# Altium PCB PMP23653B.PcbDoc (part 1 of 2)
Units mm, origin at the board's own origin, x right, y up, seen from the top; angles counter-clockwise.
Board outline 60 x 20 mm, 4 copper layers (Top Layer, Layer 2, Layer 3, Bottom Layer), stack 1.509 mm thick; 89 components, 44 nets, 290 pads, 82 vias.
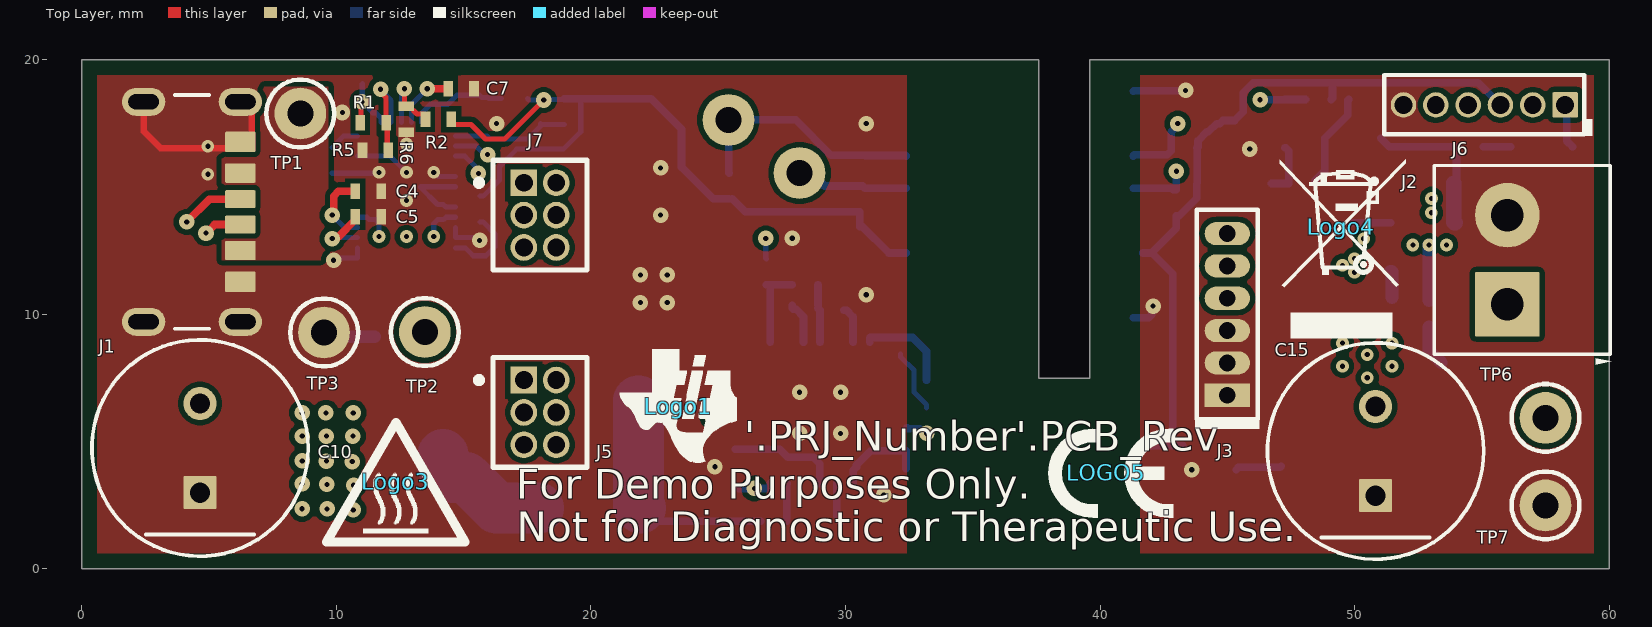
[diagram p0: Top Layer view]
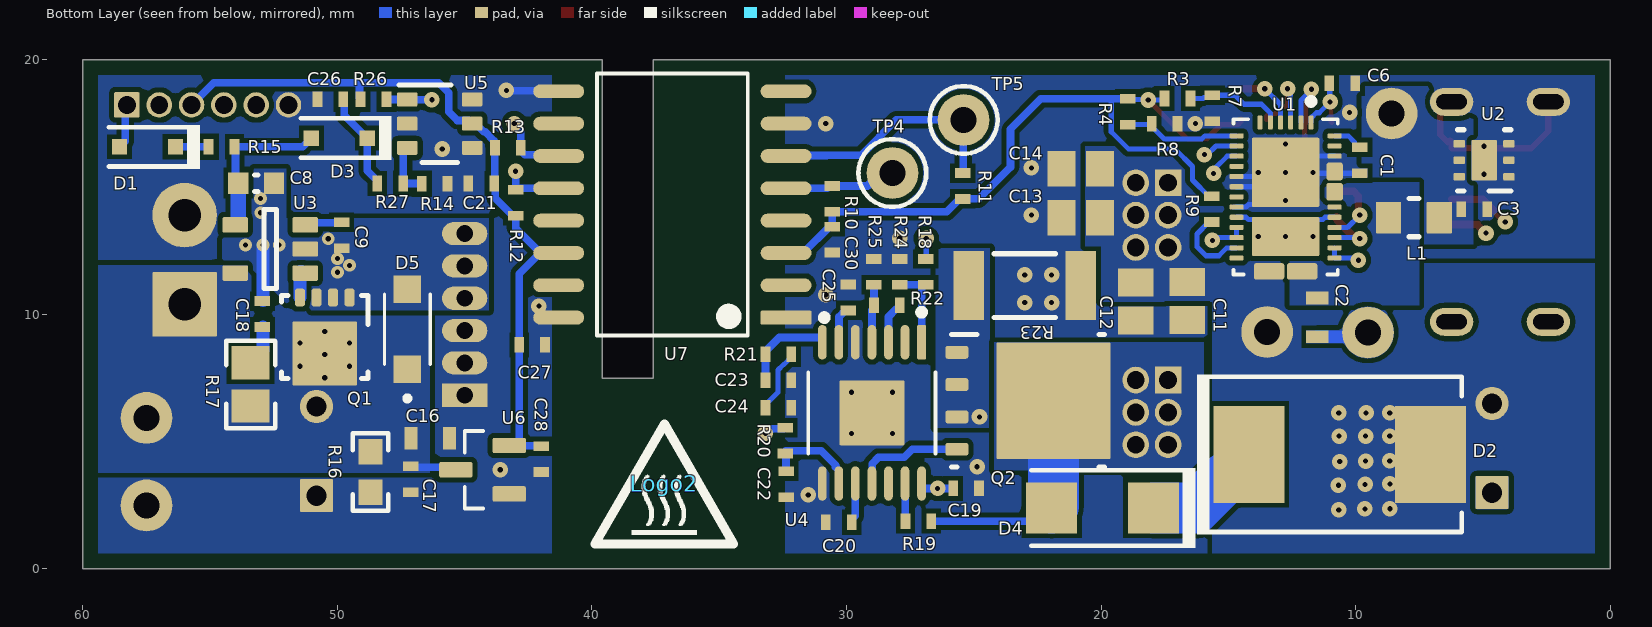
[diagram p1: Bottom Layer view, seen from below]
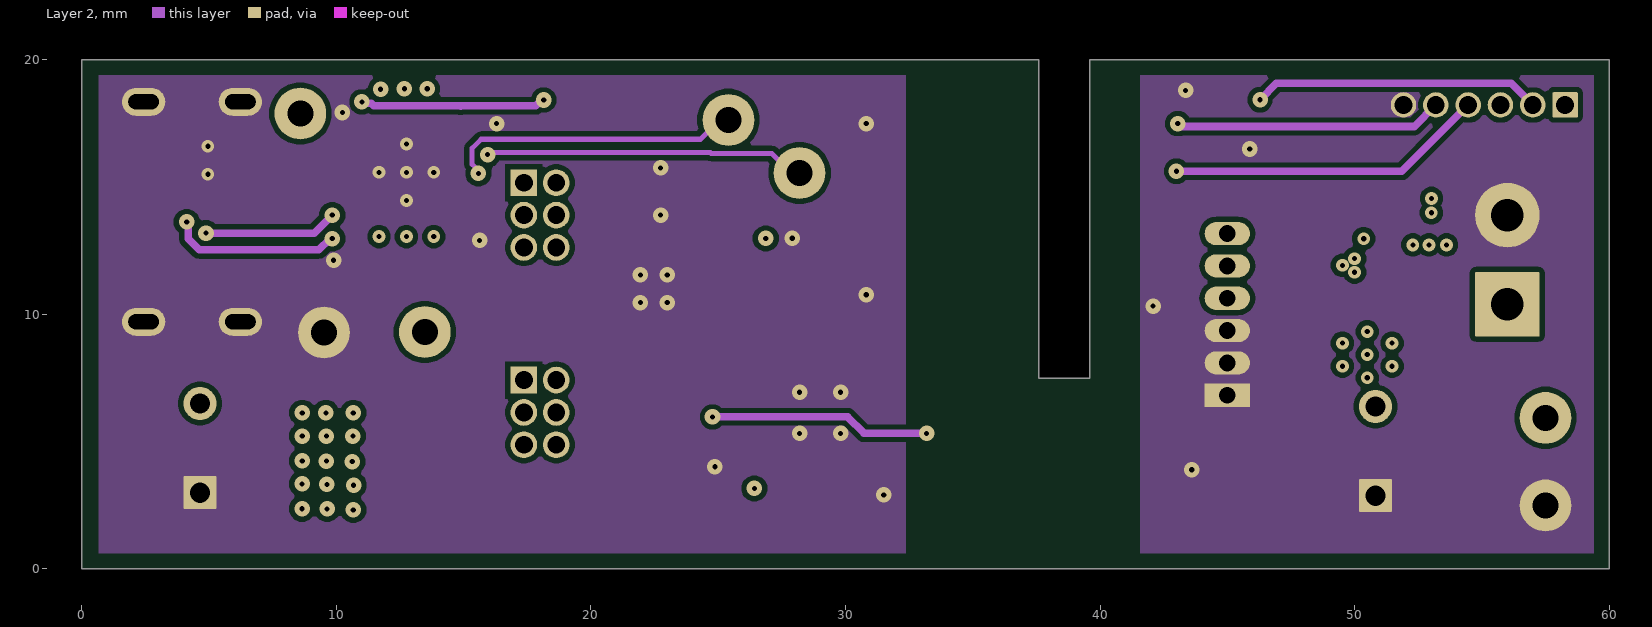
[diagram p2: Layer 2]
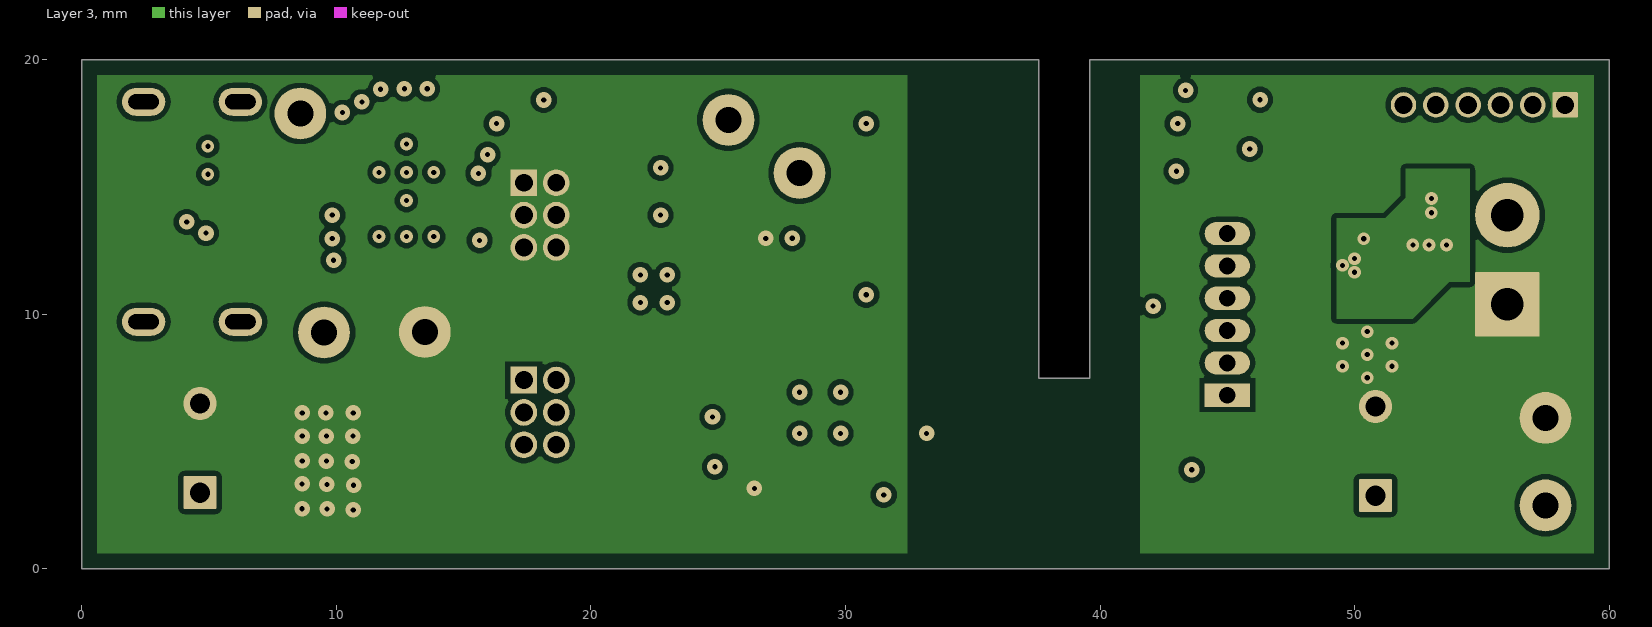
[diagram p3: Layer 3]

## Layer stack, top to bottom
Top Solder: solder mask 0.0254, SM-001, Dk 4
Top Layer: signal copper 0.07
Dielectric 1: prepreg 0.1295, PP-017, Dk 4.3
Dielectric 2: prepreg 0.1295, PP-017, Dk 4.3
Layer 2: signal copper 0.07
Dielectric 3: core 0.7112, Core-039, Dk 4.8
Layer 3: signal copper 0.07
Dielectric 4: prepreg 0.1295, PP-017, Dk 4.3
Dielectric 5: prepreg 0.1295, PP-017, Dk 4.3
Bottom Layer: signal copper 0.07
Bottom Solder: solder mask 0.0254, SM-001, Dk 4

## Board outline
0,0 0,20 37.6,20 37.6,7.5 39.6,7.5 39.6,20 60,20 60,0

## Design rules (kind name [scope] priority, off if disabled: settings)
AcuteAngle [All] p1: minimum=4.50000000000000E+0001 checktracksonly=FALSE
AssemblyTestPointUsage [All] p1: valid=2
BoardOutlineClearance BoardOutlineClearance_MountingHoles [OnCopper and InComponentClass('Mounting Holes')] p1: gap=0.6 ignorepadtopadclearanceinfootprint=FALSE
BoardOutlineClearance BoardOutlineClearance_Poly [OnCopper and IsPoly] p2: gap=0.6 ignorepadtopadclearanceinfootprint=FALSE
BoardOutlineClearance [OnCopper and Not InComponentClass('Logo') and not InComponentClass('FiducialMark') and not InRegion(1000,500,4000,800) and not InPoly] p3: gap=0.6 ignorepadtopadclearanceinfootprint=FALSE
Clearance Clearance_Keepouts [((IsTrack Or IsArc) And Not InPoly) And IsFree and IsKeepOut vs ((IsTrack Or IsArc) And Not InPoly) And IsFree and IsKeepOut] p1: gap=0 ignorepadtopadclearanceinfootprint=FALSE
Clearance Clearance_Poly [InPolygon] p2: gap=0.2 ignorepadtopadclearanceinfootprint=TRUE
Clearance Clearance_FiducialMark [IsKeepOut and InComponentClass('FiducialMark') vs IsPad and InComponentClass('FiducialMark')] p3: gap=0 ignorepadtopadclearanceinfootprint=FALSE
Clearance [All] p4: gap=0.2 ignorepadtopadclearanceinfootprint=TRUE
ComponentClearance ComponentClearance_MountingHoles_FiducialMarks [InComponentClass('Mounting Holes') vs InComponentClass('FiducialMark')] p1: gap=1.27 collisioncheckmode=3 verticalgap=0.254 showdistances=FALSE
ComponentClearance ComponentClearance_Shunt [InComponentClass('Header') vs InComponentClass('Shunt')] p2: gap=0 collisioncheckmode=3 verticalgap=0 showdistances=FALSE
ComponentClearance ComponentClearance_Logo [InComponentClass('Logo')] p3: gap=0.762 collisioncheckmode=3 verticalgap=0.254 showdistances=FALSE
ComponentClearance ComponentClearance_ScrewToNut [(HasFootprint('NY PMS 440 0025 PH')) vs (HasFootprint('Keystone_1902C'))] p4: gap=0.127 collisioncheckmode=3 verticalgap=0.254 showdistances=FALSE
ComponentClearance ComponentClearance_MountingHoles [InComponentClass('Mounting Holes')] p5: gap=2.54 collisioncheckmode=3 verticalgap=2540 showdistances=FALSE
ComponentClearance ComponentClearance_SmallPassives [HasFootprint('0201*') or HasFootprint('0402*') or HasFootprint('0508') or HasFootprint('0603*') or HasFootprint('0612') or HasFootprint('0805*') or HasFootprint('0815*') or HasFootprint('0830*') or HasFootprint('1206*') or HasFootprint('1210*') or HasFootprint('1808*') or HasFootprint('1812*') or HasFootprint('1825*') or HasFootprint('2010*') or HasFootprint('2220*') or HasFootprint('2225*') or HasFootprint('2512*') or HasFootprint('2728*') or HasFootprint('3518*') vs HasFootprint('0201*') or HasFootprint('0402*') or HasFootprint('0508') or HasFootprint('0603*') or HasFootprint('0612') or HasFootprint('0805*') or HasFootprint('0815*') or HasFootprint('0830*') or HasFootprint('1206*') or HasFootprint('1210*') or HasFootprint('1808*') or HasFootprint('1812*') or HasFootprint('1825*') or HasFootprint('2010*') or HasFootprint('2220*') or HasFootprint('2225*') or HasFootprint('2512*') or HasFootprint('2728*') or HasFootprint('3518*')] p6: gap=0.38 collisioncheckmode=3 verticalgap=0.254 showdistances=FALSE
ComponentClearance ComponentClearance_THtoSMT [IsThruComponent vs IsSMTComponent] p7: gap=0.762 collisioncheckmode=3 verticalgap=0.762 showdistances=FALSE
ComponentClearance ComponentClearance_THtoTH [IsThruComponent vs IsThruComponent] p8: gap=0.508 collisioncheckmode=3 verticalgap=0.762 showdistances=FALSE
ComponentClearance [All] p9: gap=0.508 collisioncheckmode=3 verticalgap=0.254 showdistances=FALSE
DiffPairsRouting [All] p1: maxlimit=2.54 minlimit=0.254 mostfreqgap=0.254 toplayer_minwidth=0.381 toplayer_maxwidth=0.381 toplayer_prefwidth=0.381 midlayer1_minwidth=0.381 midlayer1_maxwidth=0.381 midlayer1_prefwidth=0.381 midlayer2_minwidth=0.381 midlayer2_maxwidth=0.381 midlayer2_prefwidth=0.381 bottomlayer_minwidth=0.381 bottomlayer_maxwidth=0.381 bottomlayer_prefwidth=0.381 maxuncoupledlength=25.4
FabricationTestPointUsage TestPointUsage [All] p1: valid=2 allowmultiple=FALSE
FabricationTestpoint Testpoint [All] p1: side=3 testpointundercomponent=TRUE minsize=1.016 maxsize=2.54 preferedsize=1.524 minholesize=0 maxholesize=1.016 preferedholesize=0.813 testpointgrid=0.025 allowsidetop=TRUE allowsidebottom=TRUE usegrid=TRUE gridtolerance=0
FanoutControl Fanout_LCC [IsLCC] p1: bgadir=Out bgaviamode=Centered fanoutstyle=Auto fanoutdirection=Alternating viagrid=0.025 // Fanout_LCC (Default Rule)
FanoutControl Fanout_BGA [IsBGA] p2: bgadir=Out bgaviamode=Centered fanoutstyle=Auto fanoutdirection=Alternating viagrid=0.025 // Fanout_BGA (Default Rule)
FanoutControl Fanout_Default [All] p4: bgadir=Out bgaviamode=Centered fanoutstyle=Auto fanoutdirection=Alternating viagrid=0.025 // Fanout_Default (Default Rule)
FanoutControl Fanout_Small [(CompPinCount < 5)] p5: bgadir=Out bgaviamode=Centered fanoutstyle=Auto fanoutdirection=OutThenIn viagrid=0.025 // Fanout_Small (Default Rule)
HoleSize [All] p1: absolutevalues=TRUE maxlimit=6.375 minlimit=0.2 maxpercent=80.000 minpercent=20.000
MinimumAnnularRing MinimumAnnularRing_ThermalPadVias [IsVia and InAnyComponent] p1: minimumring=0.15
MinimumAnnularRing [All] p2: minimumring=0.12
MinimumSolderMaskSliver MinimumSolderMaskSliver_Logo [InComponentClass('Logo') vs InComponentClass('Logo')] p1: minsoldermaskwidth=0.018
MinimumSolderMaskSliver [All] p2: minsoldermaskwidth=0.1
PlaneConnect [All] p1: planeconnectstyle=Direct reliefexpansion=0.254 reliefentries=4 reliefconductorwidth=0.254 reliefairgap=0.254
PolygonConnect [All] p1: connectstyle=Direct reliefconductorwidth=0.254 reliefentries=4 polygonreliefangle="90 Angle" airgapwidth=0.254
RoutingVias ThermalPadVias [IsVia and InAnyComponent] p1: holewidth=0.2 width=0.5 viastyle="Through Hole" minholewidth=0.2 minwidth=0.5 maxholewidth=0.33 maxwidth=0.6
RoutingVias [All] p2: holewidth=0.406 width=0.864 viastyle="Through Hole" minholewidth=0.2 minwidth=0.5 maxholewidth=1.016 maxwidth=1.651
SilkToBoardRegionClearance [Not ((IsComment or IsDesignator) And (Hide <> 'False')) and not InRegion(1000,500,4000,800)] p1:
SilkToSilkClearance SilkToSilkClearance_Pb-FreeLogo [(HasFootprint('Pb-Free_Overlay_Medium') OR HasFootprint('Pb-Free_Overlay_Small')) vs (HasFootprint('Pb-Free_Overlay_Medium') OR HasFootprint('Pb-Free_Overlay_Small'))] p1: silktosilkclearance=0
SilkToSilkClearance [All] p2: silktosilkclearance=0.1
SilkToSolderMaskClearance SilkToComponentPadClearance [(IsPad or IsFill or IsRegion) and InAnycomponent] p1: minsilkscreentomaskgap=0.02 clearancetoexposedcopper=TRUE
SilkToSolderMaskClearance "Silk to Solder Mask Opening" [All] p2: minsilkscreentomaskgap=0 clearancetoexposedcopper=FALSE
SolderMaskExpansion [All] p1: expansion=0.05 istentingtop=FALSE
UnRoutedNet [All] p1: checkbadconnections=TRUE
Width [All] p1: maxlimit=2.54 minlimit=0.152 preferedwidth=0.254 checkconnectedcopper=TRUE
14 further rules are at their usual default settings.

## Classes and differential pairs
component class Header: J5 J6 J7
component class PMP23653B_sheet1: C1 C2 C3 C4 C5 C6 C7 J1 L1 R1 R2 R3 R4 R5 R6 R7 R8 R9 R10 R11 TP1 U1 U2
component class Logo: Logo1
component class PMP23653B_sheet2: C8 C9 C10 C11 C12 C13 C14 C15 C16 C17 C18 C19 C20 C21 C22 C23 C24 C25 C26 C27 C28 C30 D1 D2 D3 D4 D5 J2 J3 J5 J6 J7 Logo1 Logo2 Logo3 Logo4 LOGO5 Q1 Q2 R12 R13 R14 R15 R16 R17 R18 R19 R20 R21 R22 R23 R24 R25 R26 R27 TP2 TP3 TP4 TP5 TP6 TP7 U3 U4 U5 U6 U7

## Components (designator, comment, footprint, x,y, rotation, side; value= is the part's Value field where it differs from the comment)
C1 "GRM155R61A106ME44" 0402_070 9.836,16.055 r90 bottom value=10uF
C2 "GRM188R6YA475KE15D" 0603S 11.5,9.883 r270 bottom value=4.7uF
C3 "C1005X7R1H104K050BB" 0402S 5.338,14.122 r180 bottom value=0.1uF
C4 "GRM1555C1H331FA01J" 0402S 11.25,14.831 r180 top value=330pF
C5 "GRM1555C1H331FA01J" 0402S 11.25,13.831 r180 top value=330pF
C6 "GRM155R61A106ME44" 0402_070 10.525,19.072 r0 bottom value=10uF
C7 "GRM155R61A106ME44" 0402_070 14.9,18.862 r180 top value=10uF
C8 "GRM188R71H224KAC4D" 0603L 53.19,15.159 r180 bottom value=0.22uF
C9 "GRM155R61E225KE11D" 0402_070 49.833,13.109 r270 bottom value=2.2uF
C10 "16SEPC180MX" FP-16SEPC180MX_RADIAL-MFG 4.641,4.75 r90 top
C11 "GRM21BR61E226ME44L" 0805L 16.615,10.53 r270 bottom value=22uF
C12 "GRM21BR61E226ME44L" 0805L 18.635,10.506 r270 bottom value=22uF
C13 "GRM21BR61E226ME44L" 0805L 20.8,13.795 r0 bottom value=22uF
C14 "GRM21BR61E226ME44L" 0805L 20.8,15.726 r0 bottom value=22uF
C15 "16SEPC180MX" FP-16SEPC180MX_RADIAL-MFG 50.821,4.631 r90 top
C16 "C1608X5R1E106M080AC" 0603S 46.354,5.131 r0 bottom value=10uF
C17 "CC0402KRX7R8BB104" 0402S 47.116,3.521 r90 bottom value=0.1uF
C18 "GRM1555C1H101JA01D" 0402S 52.945,10.016 r90 bottom value=100pF
C19 "GRM155R61E105MA12D" 0402S 25.3,3.163 r0 bottom value=1uF
C20 "GRM155R61E105MA12D" 0402S 30.305,1.834 r180 bottom value=1uF
C21 "GRM155R61E105MA12D" 0402S 44.35,15.143 r180 bottom value=1uF
C22 "GRM1555C1H101JA01D" 0402S 32.374,3.327 r90 bottom value=100pF
C23 "GRM1555C1H470JZ01" 0402S 32.674,7.42 r180 bottom value=47pF
C24 "GRM155R61C273KA01D" 0402S 32.674,6.334 r180 bottom value=0.027uF
C25 "04023C103JAT2A" 0402S 29.924,10.664 r270 bottom value=0.01uF
C26 "GRM155R71H222KA01D" 0402S 50.275,18.445 r0 bottom value=2200pF
C27 "CC0402KRX7R8BB104" 0402S 42.35,8.8 r0 bottom value=0.1uF
C28 "GRM155R61A106ME44" 0402_070 42,4.315 r90 bottom value=10uF
C30 "CC0402KRX7R8BB104" 0402S 30.553,12.936 r90 bottom value=0.1uF
D1 "BAS16J,135" SOD-323F 57.461,16.586 r0 bottom value=100V
D2 "SMCJ22A-TR" SMC 10.625,4.5 r180 bottom value=22V
D3 "BAS16J,135" SOD-323F 49.923,16.925 r0 bottom value=100V
D4 "MURA110T3G" SMA 19.942,2.397 r0 bottom value=100V
D5 "60V" SODFL3718X102N 47.251,9.415 r90 bottom
J1 "USB4125-GF-A-0190" FP-USB4125-GF-A-0190_CONN_USB-MFG 3.226,14.03 r270 top
J2 "ED555/2DS" TERM_BLK_ED555-2DS 56,10.393 r90 top
J3 "851-43-006-10-001000" Mill-Max_851-XX-006-10-001000 45,10 r270 top
J5 "GRPB032VWVN-RC" Sullins_GRPB032VWVN-RC 18,6.15 r0 top
J6 "GRPB061VWVN-RC" Sullins_GRPB061VWVN-RC 55.095,18.23 r180 top
J7 "GRPB032VWVN-RC" Sullins_GRPB032VWVN-RC 18,13.9 r0 top
L1 "FBMJ2125HM210NT" 0805_HV1 7.707,13.8 r0 bottom value="21 ohm"
Logo1 "Texas Instruments" TI_Symbol_Overlay_Small 23.428,6.395 r0 top
Logo2 "CAUTION HOT SURFACE" IEC_HotSurface_Small 37.156,3.349 r180 bottom
Logo3 "CAUTION HOT SURFACE" IEC_HotSurface_Small 12.333,3.416 r0 top
Logo4 "WEEE logo" WEEE_Minimum 49.483,13.444 r0 top
LOGO5 "CE Mark" CE_Mark_3MM5 40.25,3.78 r0 top
Q1 "CSD18543Q3A" DNH0008A 50.496,9.115 r270 bottom value=60V
Q2 "CSD18514Q5A" DQJ0008A 22.87,6.607 r180 bottom value=40V
R1 "CRCW040210K0FKED" 0402S 11.445,17.536 r0 top value=10.0k
R2 "CRCW0402200KFKED" 0402S 14.005,17.666 r0 top value=200k
R3 "CRCW040243K2FKED" 0402S 16.995,18.482 r0 bottom value=43.2k
R4 "CRCW0402200KFKED" 0402S 18.96,17.964 r90 bottom value=200k
R5 "CRCW04020000Z0ED" 0402S 11.532,16.452 r0 top value=0
R6 "CRCW040210K0FKED" 0402S 12.75,17.666 r270 top value=10.0k
R7 "CRCW040210K0FKED" 0402S 15.627,18.101 r270 bottom value=10.0k
R8 "CRCW040210K0FKED" 0402S 17.503,17.495 r180 bottom value=10.0k
R9 "CRCW04020000Z0ED" 0402S 15.651,14.137 r90 bottom value=0
R10 "CRCW04023K32FKED" 0402S 30.553,14.537 r270 bottom value=3.32k
R11 "CRCW04023K32FKED" 0402S 25.433,15.045 r270 bottom value=3.32k
R12 "CRCW04023K32FKED" 0402S 43,14.385 r270 bottom value=3.32k
R13 "CRCW04023K32FKED" 0402S 43.3,16.545 r0 bottom value=3.32k
R14 "CRCW04027K50FKED" 0402S 46.18,15.136 r0 bottom value=7.50k
R15 "CRCW04024R70JNED" 0402S 54.552,16.586 r0 bottom value=4.7
R16 "CRCW06034K02FKEA" 0603 48.699,3.807 r90 bottom value=4.02k
R17 "CRCW0805100RJNEA" 0805 53.408,7.25 r270 bottom value=100
R18 "CRCW04020000Z0ED" 0402S 26.89,11.67 r270 bottom value=0
R19 "CRCW040260K4FKED" 0402S 27.175,1.88 r180 bottom value=60.4k
R20 "CRCW0402100RJNED" 0402S 32.415,5.04 r90 bottom value=100
R21 "CRCW040210K5FKED" 0402S 32.674,8.438 r180 bottom value=10.5k
R22 "CRCW0402301KFKED" 0402S 28.414,10.354 r180 bottom value=301k
R23 "PMR50HZPFU5L00" 2010L 23,11.133 r0 bottom value=0.005
R24 "CRCW040210K0FKED" 0402S 27.906,11.67 r90 bottom value=10.0k
R25 "CRCW040210K0FKED" 0402S 28.922,11.67 r90 bottom value=10.0k
R26 "CRCW0402301KFKED" 0402S 48.581,18.445 r0 bottom value=301k
R27 "CRCW0402649KFKED" 0402S 47.923,15.143 r0 bottom value=649k
TP1 "5000" Keystone5000 8.584,17.891 r90 top
TP2 "5000" Keystone5000 13.475,9.307 r90 top
TP3 "5001" Keystone5001 9.516,9.289 r90 top
TP4 "5002" Keystone5002 28.195,15.555 r90 bottom
TP5 "5002" Keystone5002 25.4,17.641 r90 bottom
TP6 "5000" Keystone5000 57.5,5.936 r90 top
TP7 "5001" Keystone5001 57.5,2.497 r90 top
U1 "TPS25730DREFR" REF0038A-MFG 12.75,14.616 r270 bottom
U2 "TVS2200DRVR" DRV0006A 4.95,16.055 r0 bottom
U3 "UCC24612-1DBVR" DBV0005A_N 52.638,12.569 r0 bottom
U4 "LM25185PWPR" PWP0014G-IPC_C 29,6.132 r270 bottom
U5 "TLV6703DDCR" DDC0006A_L 45.981,17.495 r180 bottom
U6 "TLV70933DBZR" DBZ0003A-MFG 44.299,3.9 r0 bottom
U7 "ISO1640DWR" DW0016A-IPC_C 36.84,14.32 r0 bottom

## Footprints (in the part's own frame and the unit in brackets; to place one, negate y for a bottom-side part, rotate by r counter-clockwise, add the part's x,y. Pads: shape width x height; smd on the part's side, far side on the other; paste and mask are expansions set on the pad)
0402_070 [mil] "SMD, 2-Leads, Body 1.2x0.7mm, Height 0.7mm"
  rect 15x24 smd: 1(-20,0) 2(20,0)
  body extent -24,-14 24,14, height 28
0402S [mil] "Based on C0402S footprint from PADS legacy"
  rect 15x24 smd: 1(-20,0) 2(20,0)
  body extent -22,-12 22,12, height 24
0603 [mm] "0603 from SM-752 data"
  rect 1x0.95 smd: 1(-0.8,0) 2(0.8,0)
  silkscreen extent -1.52,-0.69 1.52,0.69, body extent -0.87,-0.47 0.87,0.47, height 1
0603L [mm] "0603 from SM-752 data"
  rect 0.8x0.85 smd: 1(-0.7,0) 2(0.7,0)
  silkscreen extent -0.07,-0.33 0.07,0.33, body extent -0.87,-0.47 0.87,0.47, height 1
0603S [mil]
  rect 20x35 smd: 1(-30,0) 2(30,0)
  body extent -34,-19 34,19, height 39
0805 [mm] "0805 from SM-752 data"
  rect 1.3x1.5 smd: 1(-0.85,0) 2(0.85,0)
  silkscreen extent -1.72,-0.97 1.72,0.97, body extent -1.1,-0.72 1.1,0.72, height 1.45
0805_HV1 [mm] "Custom footprint based on analyzing multiple manufacturer recommendations"
  rrect10% 1x1.25 smd: 1(-1,0) 2(1,0)
  silkscreen extent -0.2,-0.75 0.2,0.75, body extent -1.1,-0.72 1.1,0.73, height 1.45
0805L [mm] "0805 from SM-752 data"
  rect 1.1x1.4 smd: 1(-0.75,0) 2(0.75,0)
  body extent -1.1,-0.72 1.1,0.72, height 1.45
2010L [mm]
  rect 1.2x2.7 smd: 1(-2.2,0) 2(2.2,0)
  silkscreen extent -1.2,-1.25 1.2,1.25, body extent -2.73,-1.45 2.73,1.45, height 1.66
CE_Mark_3MM5 [mm]
  silkscreen extent -2.28,-1.77 2.62,1.73
DBV0005A_N [mm] "SOT23, 5-Leads, Body 2.9x1.6mm, Pitch 0.95mm, Lead Span 2.8mm, IPC Medium Density"
  rrect17% 1x0.6 smd: 1(-1.375,0.95) 2(-1.375,0) 3(-1.375,-0.95) 4(1.375,-0.95) 5(1.375,0.95)
  silkscreen extent -0.25,-1.55 0.25,1.55, body extent -1.42,-1.46 1.42,1.46, height 1.09
DBZ0003A-MFG [mm] "Recommended Land Pattern"
  rrect17% 1.3x0.6 smd paste+0 mask+0: 1(-1.05,0.95) 2(-1.05,-0.95) 3(1.05,0)
  silkscreen extent -0.03,-1.52 0.7,1.52, body extent -1.18,-1.46 1.18,1.46, height 1.12
DDC0006A_L [mm]
  rrect18% 0.8x0.55 smd: 1(-1.275,0.95) 2(-1.275,0) 3(-1.275,-0.95) 4(1.275,-0.95) 5(1.275,0) 6(1.275,0.95)
  silkscreen extent -1.6,-1.52 0.7,1.53, body extent -1.43,-1.48 1.43,1.49, height 0.92
DNH0008A [mm] "VSONP-8"
  rrect50% 0.7x0.4 smd paste-0.05 mask-0.05: 1(-1.55,0.975) 2(-1.55,0.325) 3(-1.55,-0.325) 4(-1.55,-0.975) 5(1.55,-0.975) 6(1.55,-0.325) 7(1.55,0.325) 8(1.55,0.975)
  rrect4% 2.51x2.55 smd paste-1.5 mask-1.5: 9(0.645,0)
  rrect14% 0.705x1.125 on Bottom Paste: 9A(-0.208,0.662) 9B(0.697,0.662) 9C(-0.208,-0.663) 9D(0.697,-0.663)
  silkscreen extent -1.62,-1.7 1.62,1.7, body extent -1.65,-1.66 1.65,1.66, height 0.91
DQJ0008A [mm] "SMD, 8-Leads, Body 5.75x4.9mm"
  rrect39% 0.91x0.51 smd paste-0.05 mask-0.05: 1(-2.795,1.905) 2(-2.795,0.635) 3(-2.795,-0.635) 4(-2.795,-1.905) 5(2.795,-1.905) 6(2.795,-0.635) 7(2.795,0.635) 8(2.795,1.905)
  rrect8% 1.58x1.25 on Bottom Paste: 9(-0.38,-1.45) 9(-0.38,0) 9(-0.38,1.45) 9(1.4,-1.45) 9(1.4,0) 9(1.4,1.45)
  rrect3% 3.48x4.47 on Bottom Solder: 9(0.55,0)
  rrect2% 4.49x4.57 smd paste-2.5 mask-2.5: 9(1.005,0)
  silkscreen extent -3,-2.6 3,2.6, body extent -3.13,-2.45 3.13,2.45, height 1.15
DRV0006A [mm] "SON, 6-Leads, Body 2x2mm, Pitch 0.65mm, Thermal Pad 1.6x1mm, TI Recommended"
  rrect33% 0.45x0.3 smd: 1(-0.975,0.65) 2(-0.975,0) 3(-0.975,-0.65) 4(0.975,-0.65) 5(0.975,0) 6(0.975,0.65)
  rrect14% 1x0.7 on Bottom Paste: 7(0,-0.45) 7(0,0.45)
  rrect10% 1x1.6 smd paste-0.5: 7(0,0)
  silkscreen extent -1.05,-1.2 1.05,1.2, body extent -1.05,-1.05 1.05,1.05, height 0.81
DW0016A-IPC_C [mm]
  rrect18% 2.003x0.542 smd paste+0 mask+0: 1(-4.465,4.445)
  rrect100% 2.003x0.542 smd paste+0 mask+0: 2(-4.465,3.175) 3(-4.465,1.905) 4(-4.465,0.635) 5(-4.465,-0.635) 6(-4.465,-1.905) 7(-4.465,-3.175) 8(-4.465,-4.445) 9(4.465,-4.445) 10(4.465,-3.175) 11(4.465,-1.905) 12(4.465,-0.635) 13(4.465,0.635) 14(4.465,1.905) 15(4.465,3.175) 16(4.465,4.445)
  silkscreen extent -6.09,-5.15 2.96,5.15, body extent -5.16,-5.15 5.16,5.15, height 2.6
FP-16SEPC180MX_RADIAL-MFG [mm]
  rrect8% 1.3x1.3 hole 0.8 paste-2539.97 mask+0: 1(-1.75,0)
  round 1.3 hole 0.8 paste-2539.97 mask+0: 2(1.75,0)
  silkscreen extent -4.25,-4.25 4.25,4.25, body extent -4.35,-4.35 4.35,4.35, height 0.25
FP-USB4125-GF-A-0190_CONN_USB-MFG [mm]
  rrect100% 1.1x1.7 hole 1.2 slot 0.6 at 0 deg paste-2539.97 mask+0: 1(-4.32,3) 2(4.32,3) 3(-4.32,-0.8) 4(4.32,-0.8)
  rrect14% 0.7x1.2 smd paste+0 mask+0: A5(-0.5,3) B5(0.5,3)
  rrect13% 0.76x1.2 smd paste+0 mask+0: A9(1.52,3) B9(-1.52,3)
  rrect13% 0.8x1.2 smd paste+0 mask+0: A12(2.75,3) B12(-2.75,3)
  silkscreen extent -4.59,0.43 4.59,1.78, body extent -4.97,-3.57 4.97,3.95, height 0.25
IEC_HotSurface_Small [mm]
  silkscreen extent -2.72,-2.36 2.72,2.35
Keystone5000 [mil] "For Keystone 500x miniature loop terminals"
  round 80 hole 40: 1(0,0)
  silkscreen extent -52,-52 52,52, body extent -49,-49 49,49, height 182
Keystone5001 [mil] "For Keystone 500x miniature loop terminals"
  round 80 hole 40: 1(0,0)
  silkscreen extent -52,-52 52,52, body extent -49,-49 49,49, height 182
Keystone5002 [mil] "For Keystone 500x miniature loop terminals"
  round 80 hole 40: 1(0,0)
  silkscreen extent -52,-52 52,52, body extent -49,-49 49,49, height 182
Mill-Max_851-XX-006-10-001000 [mil] "Mill-Max"
  rect 36x70 hole 26: 1(125,0)
  oval 36x70 hole 26: 2(75,0) 3(25,0) 4(-25,0) 5(-75,0) 6(-125,0)
  silkscreen extent -162,-50 177,50, body extent -160,-45 160,45, height 162
PWP0014G-IPC_C [mm]
  rrect29% 1.355x0.341 smd paste+0 mask+0: 1(-2.775,1.95)
  rrect100% 1.355x0.341 smd paste+0 mask+0: 2(-2.775,1.3) 3(-2.775,0.65) 4(-2.775,0) 5(-2.775,-0.65) 6(-2.775,-1.3) 7(-2.775,-1.95) 8(2.775,-1.95) 9(2.775,-1.3) 10(2.775,-0.65) 11(2.775,0) 12(2.775,0.65) 13(2.775,1.3) 14(2.775,1.95)
  rrect4% 2.558x2.548 smd paste-1000 mask+0: 15(0,0)
  silkscreen extent -4.08,-2.5 1.6,2.5, body extent -3.2,-2.5 3.2,2.5, height 1.2
REF0038A-MFG [mm]
  rrect50% 0.55x0.2 smd paste+0 mask+0: 1(-2.925,1) 2(-2.925,0.6) 3(-2.925,0.2) 4(-2.925,-0.2) 5(-2.925,-0.6) 6(-2.925,-1)
  rrect50% 0.2x0.55 smd paste+0 mask+0: 7(-2.4,-1.925) 8(-2,-1.925) 9(-1.6,-1.925) 10(-1.2,-1.925) 11(-0.8,-1.925) 12(-0.4,-1.925) 13(0,-1.925) 14(0.4,-1.925) 15(0.8,-1.925) 16(1.2,-1.925) 17(1.6,-1.925) 18(2,-1.925) 19(2.4,-1.925) 26(2.4,1.925) 27(2,1.925) 28(1.6,1.925) 29(1.2,1.925) 30(0.8,1.925) 31(0.4,1.925) 36(-1.6,1.925) 37(-2,1.925) 38(-2.4,1.925)
  rrect31% 0.65x1.2 smd paste-1000 mask-1000: 20(2.925,-0.65) 23(2.925,0.65)
  rrect50% 0.55x0.2 smd paste-1000 mask-1000: 21(2.925,-0.65) 22(2.925,-0.2) 24(2.925,0.65) 25(2.925,1.1)
  rrect31% 0.7x0.65 smd paste-1000 mask-1000: 32(-0.2,1.925) 34(-1,1.925)
  rrect50% 0.2x0.55 smd paste-1000 mask-1000: 33(-0.4,1.925) 35(-1.2,1.925)
  rrect4% 2.72x2.65 smd paste-1000 mask+0: 39(-0.965,0)
  rrect7% 1.53x2.65 smd paste-1000 mask+0: 40(1.56,0)
  silkscreen extent -3.87,-2.05 3.05,2.05, body extent -3,-2 3,2, height 0.8
SMA [mm] "Molded Diode, 2-Leads, Body 4.3x2.6mm, IPC Medium Density, based on OnSemi component dimensions and land pattern"
  rect 2x2 smd: 1(-2,0) 2(2,0)
  silkscreen extent -3.66,-1.57 2.79,1.57, body extent -2.6,-1.3 2.6,1.3, height 2.42
SMC [mil] "Molded Diode, 2-Leads, Body 6.9x5.8mm, IPC Medium Density, based on OnSemi component dimensions and land patterns"
  rect 110x150 smd: 1(-140.49,0) 2(140.49,0)
  silkscreen extent -221,-123 189,124, body extent -156,-116 156,116, height 91
SOD-323F [mm] "NXP recommended land pattern"
  rect 0.6x0.6 smd paste-0.05: 1(-1.1,0) 2(1.1,0)
  silkscreen extent -2.06,-0.86 1.53,0.86, body extent -1.35,-0.67 1.35,0.67, height 0.79
SODFL3718X102N [mm]
  rect 1.08x1.09 smd: A(1.575,0) C(-1.575,0)
  silkscreen extent -2.81,-0.9 1.38,0.9, body extent -1.85,-0.9 1.85,0.9, height 1.03
Sullins_GRPB032VWVN-RC [mm] "Sullins"
  rect 1.05x1.05 hole 0.7 paste-2539.97: 1(-0.635,1.27)
  round 1.05 hole 0.7 paste-2539.97: 2(0.635,1.27) 3(-0.635,0) 4(0.635,0) 5(-0.635,-1.27) 6(0.635,-1.27)
  silkscreen extent -2.51,-2.15 1.85,2.15, body extent -1.85,-2.15 1.85,2.15, height 4
Sullins_GRPB061VWVN-RC [mm] "SULLINS"
  rrect10% 1x1 hole 0.7: 1(-3.175,0)
  round 1 hole 0.7: 2(-1.905,0) 3(-0.635,0) 4(0.635,0) 5(1.905,0) 6(3.175,0)
  silkscreen extent -4.25,-1.17 3.93,1.23, body extent -3.85,-1.1 3.85,1.1, height 4.3
TERM_BLK_ED555-2DS [mil]
  rrect4% 100x100 hole 50: 1(0,0)
  round 100 hole 50: 2(138,0)
  silkscreen extent -93,-161 215,113, body extent -69,-150 207,106, height 323
TI_Symbol_Overlay_Small [mm]
  silkscreen extent -2.3,-2.23 2.3,2.24
WEEE_Minimum [mm] "WEEElie bin"
  silkscreen extent -2.42,-4.38 2.52,2.65

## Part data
C1 C6 C7 C28: library part CMP-0074692-1, "CAP, CERM, 10 µF, 10 V,+/- 20%, X5R, 0402", Cap_Case=0402, Manufacturer=MuRata, TempCo=X5R, Tolerance_%=20%, Value2=10V, ValueDisplayed=10µF
C2: library part CMP-0007357-5, "CAP, CERM, 4.7 uF, 35 V, +/- 10%, X5R, 0603", Cap_Case=0603, Manufacturer=MuRata, Supplier Part Number 1=490-7205-1-ND, TempCo=X5R, Tolerance_%=10%, Value1=Unknown, Value2=35V, ValueDisplayed=4.7uF
C3: library part CMP-0006297-2, "CAP, CERM, 0.1 uF, 50 V, +/- 10%, X7R, 0402", Cap_Case=0402, Manufacturer=TDK, Supplier Part Number 1=445-5932-1-ND, TempCo=X7R, Tolerance_%=10%, Value1="0.039064 ohm", Value2=50V, ValueDisplayed=0.1uF
C4 C5: library part CMP-0006455-2, "CAP, CERM, 330 pF, 50 V, +/- 1%, C0G/NP0, 0402", Cap_Case=0402, Manufacturer=MuRata, Supplier Part Number 1=490-6234-1-ND, TempCo=C0G/NP0, Tolerance_%=1%, Value1=Unknown, Value2=50V, ValueDisplayed=330pF
C8: library part CMP-0007445-4, "CAP, CERM, 0.22 uF, 50 V, +/- 10%, X7R, 0603", Cap_Case=0603, Manufacturer=MuRata, Supplier Part Number 1=490-12546-1-ND, TempCo=X7R, Tolerance_%=10%, Value1=Unknown, Value2=50V, ValueDisplayed=0.22uF
C9: library part CMP-0006610-2, "CAP, CERM, 2.2 uF, 25 V, +/- 10%, X5R, 0402", Cap_Case=0402, Manufacturer=MuRata, Supplier Part Number 1=GRM155R61E225KE11D-ND, TempCo=X5R, Tolerance_%=10%, Value1=Unknown, Value2=25V, ValueDisplayed=2.2uF
C10 C15: library part CMP-0089787-1, "180µF 16V Aluminum - Polymer Capacitors Radial, Can 10mOhm 5000 Hrs @ 105°C", Digikey Part Number=P16295-ND, Leakage Current=576uA, Manufacturer=Panasonic, Mouser Part Number=667-16SEPC180MX, Operating Temperature Range="-55°C to +105°C", Tolerance_%=20%, ValueDisplayed=180uF
C11 C12 C13 C14: library part CMP-0008305-2, "CAP, CERM, 22 uF, 25 V, +/- 20%, X5R, 0805", Cap_Case=0805, Manufacturer=MuRata, Supplier Part Number 1=490-10749-1-ND, TempCo=X5R, Tolerance_%=20%, Value1=Unknown, Value2=25V, ValueDisplayed=22uF
C16: library part CMP-0007007-5, "CAP, CERM, 10 uF, 25 V, +/- 20%, X5R, 0603", Cap_Case=0603, Manufacturer=TDK, Supplier Part Number 1=445-9015-1-ND, TempCo=X5R, Tolerance_%=20%, Value1="0.004639 ohm", Value2=25V, ValueDisplayed=10uF
C17 C27 C30: library part CMP-0860555-1, "CAP, CERM, 0.1 µF, 25 V,+/- 10%, X7R, 0402", Cap_Case=0402, Manufacturer=Yageo, TempCo=X7R, Tolerance_%=10%, Value2=25V, ValueDisplayed=0.1µF
C18 C22: library part CMP-0006410-2, "CAP, CERM, 100 pF, 50 V, +/- 5%, C0G/NP0, 0402", Cap_Case=0402, Manufacturer=MuRata, Supplier Part Number 1=81-GRM1555C1H101JA1D, TempCo=C0G/NP0, Tolerance_%=5%, Value1=Unknown, Value2=50V, ValueDisplayed=100pF
C19 C20 C21: library part CMP-0078625-1, "CAP, CERM, 1 µF, 25 V,+/- 20%, X5R, 0402", Cap_Case=0402, Manufacturer=MuRata, Supplier Part Number 1=490-10018-1-ND, TempCo=X5R, Tolerance_%=20%, Value2=25V, ValueDisplayed=1µF
C23: library part CMP-0006469-2, "CAP, CERM, 47 pF, 50 V, +/- 5%, C0G/NP0, 0402", Cap_Case=0402, Manufacturer=MuRata, Supplier Part Number 1=490-1287-1-ND, TempCo=C0G/NP0, Tolerance_%=5%, Value1="0.045 ohm", Value2=50V, ValueDisplayed=47pF
C24: library part CMP-0006595-2, "CAP, CERM, 0.027 uF, 16 V, +/- 10%, X5R, 0402", Cap_Case=0402, Manufacturer=MuRata, Supplier Part Number 1=GRM155R61C273KA01D-ND, TempCo=X5R, Tolerance_%=10%, Value1=Unknown, Value2=16V, ValueDisplayed=0.027uF
C25: library part CMP-0085568-1, "CAP, CERM, 0.01 µF, 25 V,+/- 5%, X7R, 0402", Cap_Case=0402, Manufacturer=AVX, TempCo=X7R, Tolerance_%=5%, Value2=25V, ValueDisplayed=0.01µF
C26: library part CMP-0006683-2, "CAP, CERM, 2200 pF, 50 V, +/- 10%, X7R, 0402", Cap_Case=0402, Manufacturer=MuRata, Supplier Part Number 1=490-1305-1-ND, TempCo=X7R, Tolerance_%=10%, Value1=Unknown, Value2=50V, ValueDisplayed=2200pF
D1 D3: library part CMP-0076955-2, "Diode, Switching, 100 V, 0.25 A, SOD-323F", Manufacturer=Nexperia, Value1=0.25A, Value2=V
D2: library part CMP-0085427-1, "Diode, TVS, Uni, 22 V, 35.5 Vc, 1500 W, 44 A, SMC", Manufacturer=STMicroelectronics, Value1=35.5V
D4: library part CMP-0029196-2, "Diode, Ultrafast, 100 V, 2 A, SMA", Manufacturer="ON Semiconductor", Value1=2A, Value2=V
D5: library part TSSW3U60, "DIODE SCHOTTKY 60V 3A SOD123W", Manufacturer="Taiwan Semiconductor Corporation", Package=None
J1: library part CMP-0094557-1, "24 (6+18 Dummy) Position USB-C (USB TYPE-C) USB 2.0 Receptacle Connector", Current_A=3A, Digikey Part Number=2073-USB4125-GF-A-0190CT-ND, Manufacturer=GCT, Mouser Part Number=640-USB4125-GF-A-190, Operating Temperature Range="-30°C to +85°C", Voltage_V=20V
J2: library part CMP-0074913-1, "Terminal Block, 3.5mm Pitch, 2x1, TH", Color=Grey, Current_A=6A, Manufacturer="On-Shore Technology", Supplier Part Number 1=ED1514-ND, Voltage_V=150V
J3: library part CMP-0055069-1, "Receptacle, 50mil, 6x1, Gold, TH", Manufacturer=Mill-Max, Supplier Part Number 1=ED90529-ND
J5 J7: library part CMP-0054557-2, "Header, 50mil, 3x2, Gold, TH", Manufacturer="Sullins Connector Solutions", Supplier Part Number 1=S9015E-03-ND
J6: library part CMP-0054561-1, "Header, 50mil, 6x1, Gold,  TH", Manufacturer="Sullins Connector Solutions", Supplier Part Number 1=S9014E-06-ND
L1: library part CMP-0003375-1, "Ferrite Bead, 21 ohm @ 100 MHz, 6 A, 0805", Manufacturer="Taiyo Yuden", Supplier Part Number 1=587-1765-1-ND, Value1="0.004 ohm", Value2=6A, ValueDisplayed="21 ohm"
Logo1: library part CMP-0074838-1, "Texas Instrument Corporate Signature"
Logo2 Logo3: library part CMP-0074837-2, "IEC 61010-1 Hot Surface Warning", Manufacturer="Texas Instruments"
Logo4: library part CMP-0074769-4, Manufacturer="Texas Instruments"
LOGO5: library part CMP-0074844-2, Manufacturer="Texas Instruments"
Q1: library part CMP-0000826-2, "MOSFET, N-CH, 60 V, 35 A, DNH0008A (VSONP-8)", Alternate Manufacturer=None, Manufacturer="Texas Instruments", Supplier Part Number 1=CSD18543Q3A-ND, Value1=0.01, Value2="11.1 nC"
Q2: library part CMP-0000715-1, "MOSFET, N-CH, 40 V, 50 A, DQJ0008A (VSONP-8)", Alternate Manufacturer=None, Manufacturer="Texas Instruments", Supplier Part Number 1=CSD18514Q5A-ND, Value1=0.007, Value2="29 nC"
R1 R6 R7 R8 R24 R25: library part CMP-0025958-3, "RES, 10.0 k, 1%, 0.063 W, AEC-Q200 Grade 0, 0402", Manufacturer=Vishay-Dale, Power_W=63mW, Supplier Part Number 1=541-10.0KLCT-ND, TempCo="100 ppm/C", Tolerance_%=1%, Value2=0.063W, Value_Code=10k0, ValueDisplayed=10.0k
R2 R4: library part CMP-0026158-2, "RES, 200 k, 1%, 0.063 W, AEC-Q200 Grade 0, 0402", Manufacturer=Vishay-Dale, Power_W=63mW, Supplier Part Number 1=541-200KLCT-ND, TempCo="100 ppm/C", Tolerance_%=1%, Value2=0.063W, Value_Code=200k
R3: library part CMP-0026379-2, "RES, 43.2 k, 1%, 0.063 W, AEC-Q200 Grade 0, 0402", Manufacturer=Vishay-Dale, Power_W=63mW, Supplier Part Number 1=541-43.2KLCT-ND, TempCo="100 ppm/C", Tolerance_%=1%, Value2=0.063W, Value_Code=43k2, ValueDisplayed=43.2k
R5 R9 R18: library part CMP-0026822-3, "RES, 0, 5%, 0.063 W, AEC-Q200 Grade 0, 0402", Manufacturer=Vishay-Dale, Power_W=63mW, Supplier Part Number 1=541-0.0JCT-ND, TempCo="200 ppm/C", Tolerance_%=5%, Value2=0.063W, Value_Code=0000, ValueDisplayed=0
R10 R11 R12 R13: library part CMP-0026333-2, "RES, 3.32 k, 1%, 0.063 W, AEC-Q200 Grade 0, 0402", Manufacturer=Vishay-Dale, Power_W=63mW, Supplier Part Number 1=541-3.32KLCT-ND, TempCo="100 ppm/C", Tolerance_%=1%, Value2=0.063W, Value_Code=3k32, ValueDisplayed=3.32k
R14: library part CMP-0026555-2, "RES, 7.50 k, 1%, 0.063 W, AEC-Q200 Grade 0, 0402", Manufacturer=Vishay-Dale, Power_W=63mW, Supplier Part Number 1=541-7.50KLCT-ND, TempCo="100 ppm/C", Tolerance_%=1%, Value2=0.063W, Value_Code=7k50, ValueDisplayed=7.50k
R15: library part CMP-0026942-3, "RES, 4.7, 5%, 0.063 W, AEC-Q200 Grade 0, 0402", Manufacturer=Vishay-Dale, Power_W=63mW, Supplier Part Number 1=541-4.7JCT-ND, TempCo="200 ppm/C", Tolerance_%=5%, Value2=0.063W, Value_Code=4R70, ValueDisplayed=4.7
R16: library part CMP-0022449-4, "RES, 4.02 k, 1%, 0.1 W, AEC-Q200 Grade 0, 0603", Manufacturer=Vishay-Dale, Power_W=100mW, Supplier Part Number 1=541-4.02KHCT-ND, TempCo="100 ppm/C", Tolerance_%=1%, Value2=0.1W, Value_Code=4k02, ValueDisplayed=4.02k
R17: library part CMP-0020445-3, "RES, 100, 5%, 0.125 W, AEC-Q200 Grade 0, 0805", Manufacturer=Vishay-Dale, Power_W=125mW, Supplier Part Number 1=541-100ACT-ND, TempCo="200 ppm/C", Tolerance_%=5%, Value2=0.125W, Value_Code=100R, ValueDisplayed=100
R19: library part CMP-0026486-2, "RES, 60.4 k, 1%, 0.063 W, AEC-Q200 Grade 0, 0402", Manufacturer=Vishay-Dale, Power_W=63mW, Supplier Part Number 1=541-60.4KLCT-ND, TempCo="100 ppm/C", Tolerance_%=1%, Value2=0.063W, Value_Code=60k4, ValueDisplayed=60.4k
R20: library part CMP-0026824-3, "RES, 100, 5%, 0.063 W, AEC-Q200 Grade 0, 0402", Manufacturer=Vishay-Dale, Power_W=63mW, Supplier Part Number 1=541-100JCT-ND, TempCo="200 ppm/C", Tolerance_%=5%, Value2=0.063W, Value_Code=100R, ValueDisplayed=100
R21: library part CMP-0025960-3, "RES, 10.5 k, 1%, 0.063 W, AEC-Q200 Grade 0, 0402", Manufacturer=Vishay-Dale, Power_W=63mW, Supplier Part Number 1=541-10.5KLCT-ND, TempCo="100 ppm/C", Tolerance_%=1%, Value2=0.063W, Value_Code=10k5, ValueDisplayed=10.5k
R22 R26: library part CMP-0026280-2, "RES, 301 k, 1%, 0.063 W, AEC-Q200 Grade 0, 0402", Manufacturer=Vishay-Dale, Power_W=63mW, Supplier Part Number 1=541-301KLCT-ND, TempCo="100 ppm/C", Tolerance_%=1%, Value2=0.063W, Value_Code=301k
R23: "RES 0.005 OHM 1% 1W 2010", Manufacturer_Name="ROHM Semiconductor"
R27: library part CMP-0026496-2, "RES, 649 k, 1%, 0.063 W, AEC-Q200 Grade 0, 0402", Manufacturer=Vishay-Dale, Power_W=63mW, Supplier Part Number 1=541-649KLCT-ND, TempCo="100 ppm/C", Tolerance_%=1%, Value2=0.063W, Value_Code=649k
TP1 TP2 TP6: library part CMP-0055137-2, "Test Point, Miniature, Red, TH", Color=Red, Manufacturer="Keystone Electronics", Supplier Part Number 1=36-5000-ND
TP3 TP7: library part CMP-0055138-2, "Test Point, Miniature, Black, TH", Color=Black, Manufacturer="Keystone Electronics", Supplier Part Number 1=36-5001-ND
TP4 TP5: library part CMP-0055139-2, "Test Point, Miniature, White, TH", Color=White, Manufacturer="Keystone Electronics", Supplier Part Number 1=36-5002-ND
U1: library part CMP-0120752-1, "Sink-only USB Type-C® and USB Power Delivery (PD) controller with no firmware development required 38-WQFN -40 to 125", Manufacturer="Texas Instruments", Max Supply Voltage=22V, Min Supply Voltage=3V, Operating Temperature Range="-40°C to +125°C"
U2: library part CMP-0077834-1, "22-V Precision Surge Protection Clamp, DRV0006A (WSON-6)", Alternate Manufacturer="Texas Instruments"
U3: library part CMP-0013050-3, "High-Frequency Multi-Mode Synchronous Rectifier Controller, DBV0005A (SOT-23-5)", Alternate Manufacturer="Texas Instruments", Alternate PartNumber=UCC24612-1DBVT
U4: library part CMP-0123130-1, "42-VIN primary side regulation flyback controller with low IQ and low EMI", Digikey Part Number=296-LM25185PWPRTR-ND, Manufacturer="Texas Instruments", Max Supply Voltage=42V, Min Supply Voltage=4.5V, Mouser Part Number=595-LM25185PWPR, Nominal Supply Current=25-425uA, Operating Temperature Range="-40°C to +125°C", Switching Frequency=11-350kHz
U5: library part CMP-0084583-1, "High Voltage Comparator with Integrated Reference, DDC0006A (SOT-23-THIN-6)", Alternate Manufacturer="Texas Instruments", Alternate PartNumber=TLV6703DDCT, Operating Temperature Range="-40 to 125 C", Rating=Catalog
U6: library part CMP-0127088-1, "150-mA 30-V low-dropout (LDO) linear regulator with 3.2-μA supply current 3-SOT-23 -40 to 125", Digikey Part Number=296-TLV70933DBZRCT-ND, Dropout Voltage=1000mV, Manufacturer="Texas Instruments", Max Supply Voltage=30V, Min Supply Voltage=4.3V, Nominal Supply Current=3.2uA, Operating Temperature Range="-40°C to +125°C", Output Voltage=3.3V
U7: library part CMP-0095765-1, "I²C Digital Isolator 5000Vrms 2 Channel - 50kV/µs CMTI 16-SOIC (0.295\", 7.50mm Width)", Digikey Part Number=296-ISO1640DWRCT-ND, Manufacturer="Texas Instruments", Max Supply Voltage=5.5V, Min Supply Voltage=2.25V, Mouser Part Number=595-ISO1640DWR, Operating Temperature Range="-40°C to +125°C"

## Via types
v1: diameter 0.61, hole 0.203, Top Layer to Bottom Layer, tented both sides, 56 vias
v2: diameter 0.5, hole 0.203, Top Layer to Bottom Layer, tented both sides, 9 vias
v3: diameter 0.5, hole 0.2, Top Layer to Bottom Layer, tented both sides, 9 vias
v4: diameter 0.5, hole 0.2, Top Layer to Bottom Layer, 8 vias

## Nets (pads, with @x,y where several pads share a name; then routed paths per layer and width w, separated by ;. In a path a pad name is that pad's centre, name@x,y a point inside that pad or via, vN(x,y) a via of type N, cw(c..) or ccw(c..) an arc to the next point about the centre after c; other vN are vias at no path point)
3V3P: C6.2 C30.2 R1.1 R2.2 R3.2 R4.2 R9.2 R10.2 R11.2 U1.1 U7.3 | length 39.8
  Top Layer w0.2: R1.1@10.937,17.536 10.969,17.568 10.969,18.319 v1(11,18.35) ; R2.2@14.513,17.666 14.513,17.552 14.603,17.461 15.289,17.461 15.86,16.89 16.611,16.89 v1(18.143,18.423)
  Layer 2 w0.3: v1(11,18.35) 11.059,18.291 11.367,18.291 11.464,18.193 14.903,18.193 ; 14.882,18.172 14.903,18.193 ; v1(18.143,18.423) 18.059,18.423 17.83,18.193 14.903,18.193
  Bottom Layer w0.2: C6.2@11.033,19.072 11.017,19.055 11.017,18.367 v1(11,18.35) 11.428,17.923 11.544,17.923 11.75,17.716 U1.1@11.75,17.541 ; R9.2@15.651,14.645 15.765,14.645 16.404,15.285 16.404,15.812 17.083,16.49 18.914,16.49 19.6,17.176 19.6,18.472 ; R3.2@17.503,18.482 17.562,18.423 v1(18.143,18.423) 18.168,18.447 18.935,18.447 R4.2@18.96,18.472
  Bottom Layer w0.3: R4.2@18.96,18.472 19.6,18.472 22.366,18.472 23.559,17.279 23.559,15.776 24.799,14.537 R11.2@25.433,14.537 ; R11.2@25.547,14.537 26.055,14.029 R10.2@30.553,14.029 C30.2@30.553,13.444 ; C30.2@30.668,13.444 31.697,12.415 U7.3@32.374,12.415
